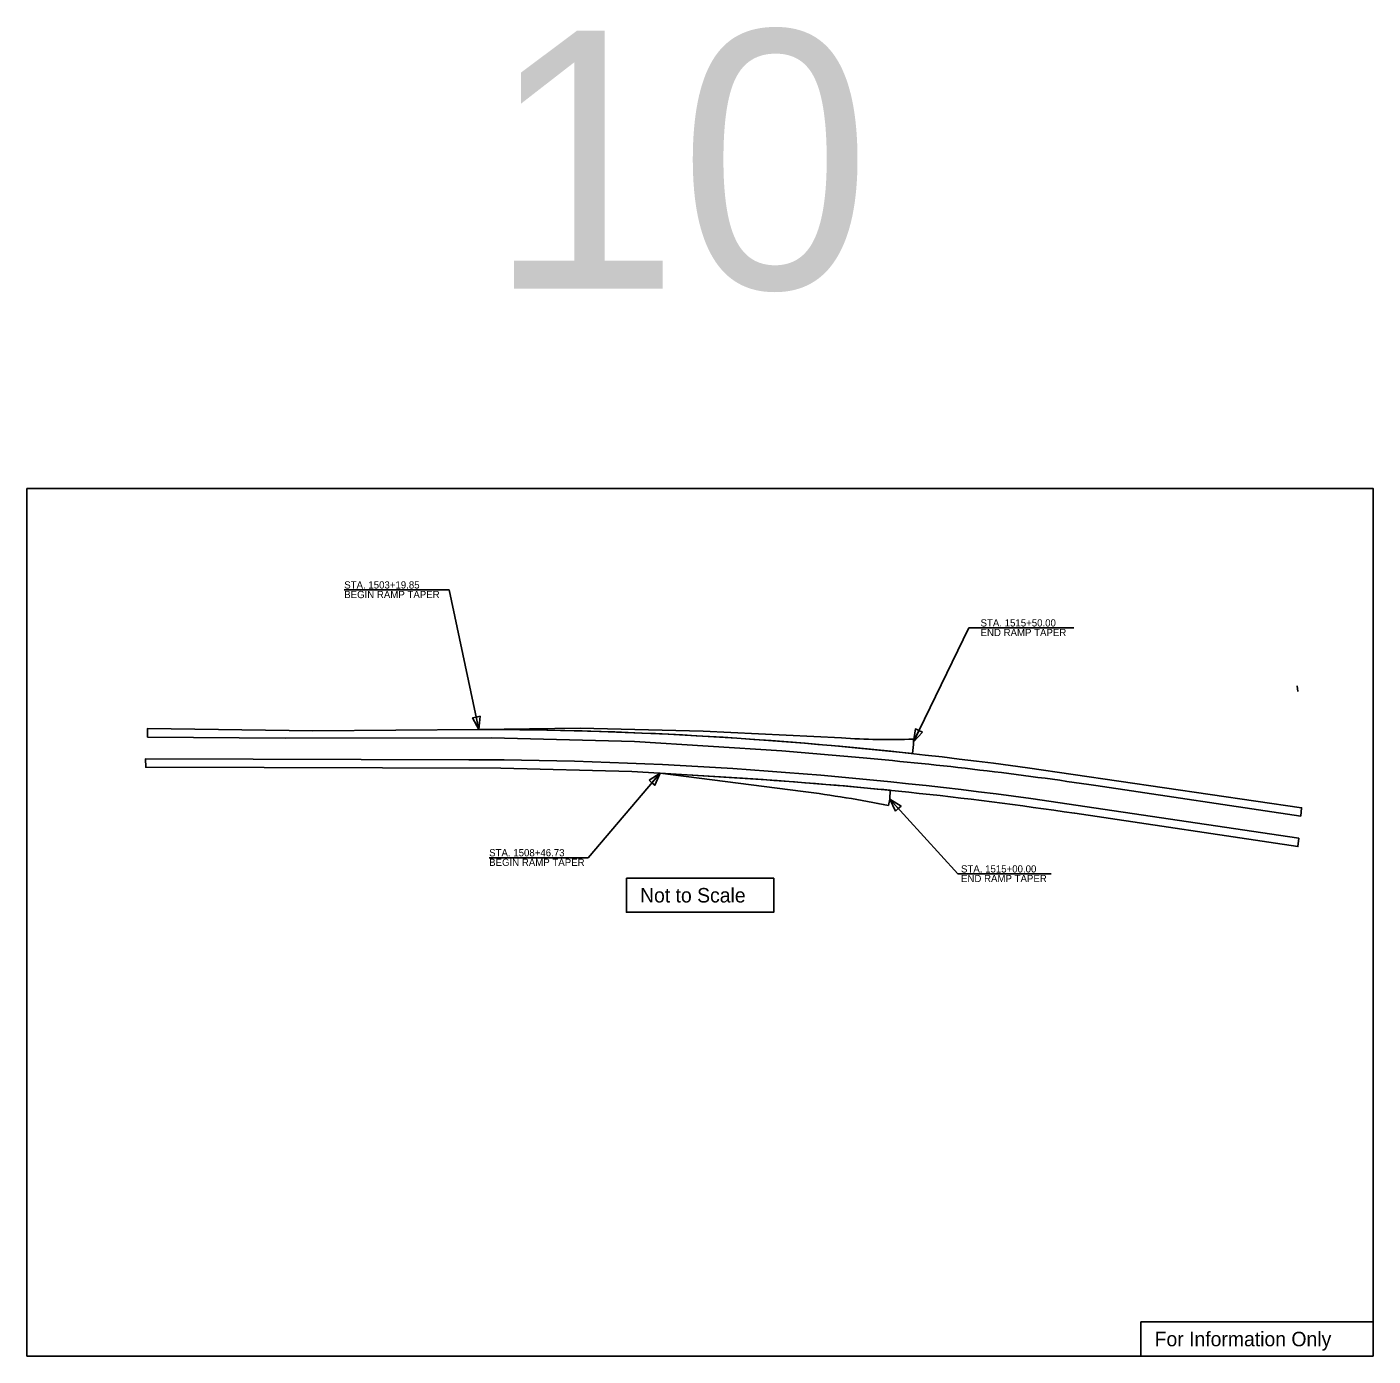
# Model space of a CAD drawing. Extents: x 10133 to 81668, y 7924 to 12255.
# Drawn here: x 42533 to 45668, y 7924 to 11018 of the extents above; entities that cross this region are included whole.
import ezdxf

# ---------------------------------------------------------------- set-up
doc = ezdxf.new("R2010")
doc.units = 0
for name, color, linetype in [('RasterAttachment', 7, 'Continuous'), ('SheetBorder', 7, 'Continuous'), ('SheetText', 7, 'Continuous'), ('Text', 7, 'Continuous')]:
    doc.layers.add(name, color=color, linetype=linetype)

msp = doc.modelspace()

# ---------------------------------------------------------------- linework, layer by layer
at = {"layer": 'RasterAttachment'}
for p, q in [((45490.4, 9483.9), (45492.4, 9470.8)), ((43585.2, 9382.9), (43820.8, 9386)), ((44595.1, 9326.5), (44597.1, 9347.7)), ((44597.1, 9347.7), (44597, 9360)), ((44007.2, 9281), (44340.2, 9238.6)), ((44542.2, 9220.2), (44539.3, 9205.7)), ((44543.2, 9241.1), (44542.2, 9220.2))]:
    msp.add_line(p, q, dxfattribs=at)
for points in [[(44480.3, 9316.4), (44290.5, 9333.2), (43947.3, 9354.5), (43614.7, 9363), (43133.9, 9362.5), (42813.5, 9364.9), (42813.2, 9384.6), (43198.2, 9379.3), (43585.2, 9382.9)], [(43585.2, 9382.9), (43820.8, 9386), (44107.1, 9379.1), (44429.5, 9363.2)], [(43820.8, 9386), (44107.1, 9379.1), (44429.5, 9363.2)], [(44597, 9360), (44597.1, 9347.7), (44595.1, 9326.5)], [(44198.9, 9269.1), (43941.5, 9285.1), (43636.2, 9292.5), (42809.3, 9294.6), (42809, 9314.4), (43561.4, 9312.3)], [(44007.2, 9281), (44279.5, 9263.7), (44421.2, 9252.5)], [(44340.2, 9238.6), (44007.2, 9281), (44279.5, 9263.7), (44421.2, 9252.5)], [(44862.7, 9293.3), (45500.9, 9200.3), (45498.9, 9181.1), (45022.2, 9252.2)], [(44543.2, 9241.1), (44542.2, 9220.2), (44539.3, 9205.7)], [(44870.8, 9221.8), (45494.6, 9129.3), (45492.6, 9110.1), (44972.6, 9187.5)]]:
    msp.add_lwpolyline(points, dxfattribs=at)
for centre, radius, start, end in [((43563.6, -77.2), 9460.1, 82.10666, 89.86892), ((43563.6, -77.2), 9460.1, 83.73996, 89.86892), ((44541.7, 10892.6), 1533.5, 265.8039, 272.0682), ((44541.7, 10892.7), 1533.6, 265.804, 272.0678), ((43534.9, -580), 9892.4, 82.23878, 89.84614), ((43682, 265.3), 9086.2, 81.51849, 84.95996), ((43634.6, 200.4), 9086.2, 81.53238, 86.43954), ((43634.6, 200.4), 9086.2, 84.26125, 85.03371), ((43922.3, 6094.7), 3171.6, 78.782, 82.4278), ((43922.3, 6094.7), 3171.6, 78.782, 82.4278)]:
    msp.add_arc(centre, radius, start, end, dxfattribs=at)
at = {"layer": 'SheetBorder'}
msp.add_lwpolyline([(42532.5, 9944), (45667.5, 9944), (45667.5, 7924), (42532.5, 7924)], close=True, dxfattribs=at)
at = {"layer": 'SheetText'}
for points in [[(43928.5, 9036.5), (44271.6, 9036.5), (44271.6, 8957.1), (43928.5, 8957.1)], [(45127, 8003.4), (45667.5, 8003.4), (45667.5, 7924), (45127, 7924)]]:
    msp.add_lwpolyline(points, close=True, dxfattribs=at)
at = {"layer": 'Text'}
for p, q in [((43516.1, 9707.4), (43271.6, 9707.4)), ((43585.2, 9382.9), (43516.1, 9707.4)), ((44597, 9353.9), (44726, 9619)), ((44970.8, 9619), (44726, 9619)), ((44007.2, 9281), (43839.6, 9084)), ((44542.2, 9220.2), (44700.2, 9046.3)), ((43839.6, 9084), (43609.1, 9084)), ((44917.5, 9046.3), (44700.2, 9046.3))]:
    msp.add_line(p, q, dxfattribs=at)
for points in [[(43585.2, 9382.9), (43570.4, 9409.7), (43579.1, 9411.5)], [(43587.9, 9413.4), (43585.2, 9382.9), (43579.1, 9411.5)], [(44597, 9353.9), (44601.8, 9384.1), (44609.8, 9380.2)], [(44617.9, 9376.3), (44597, 9353.9), (44609.8, 9380.2)], [(43981.4, 9264.5), (44007.2, 9281), (43988.2, 9258.7)], [(44007.2, 9281), (43995, 9252.9), (43988.2, 9258.7)], [(44542.2, 9220.2), (44568.4, 9204.4), (44561.8, 9198.4)], [(44555.2, 9192.4), (44542.2, 9220.2), (44561.8, 9198.4)]]:
    msp.add_lwpolyline(points, close=True, dxfattribs=at)

# ---------------------------------------------------------------- texts
at = {"layer": 'SheetText'}
for s, height, p in [('10', 600, (43605.7, 10409.2)), ('Not to Scale', 33.75, (43960.4, 8979.9)), ('For Information Only', 33.75, (45158.8, 7946.8))]:
    msp.add_text(s, height=height, dxfattribs=at).set_placement(p)
at = {"layer": 'Text'}
for s, p in [('STA. 1503+19.85', (43271.5, 9710.8)), ('BEGIN RAMP TAPER', (43271.5, 9688.4)), ('STA. 1515+50.00', (44753.4, 9622.4)), ('END RAMP TAPER', (44753.4, 9600)), ('STA. 1508+46.73', (43609, 9087.4)), ('BEGIN RAMP TAPER', (43609, 9065)), ('STA. 1515+00.00', (44707.9, 9049.7)), ('END RAMP TAPER', (44707.9, 9027.3))]:
    msp.add_text(s, height=16.8, dxfattribs=at).set_placement(p)

doc.saveas('drawing.dxf')
